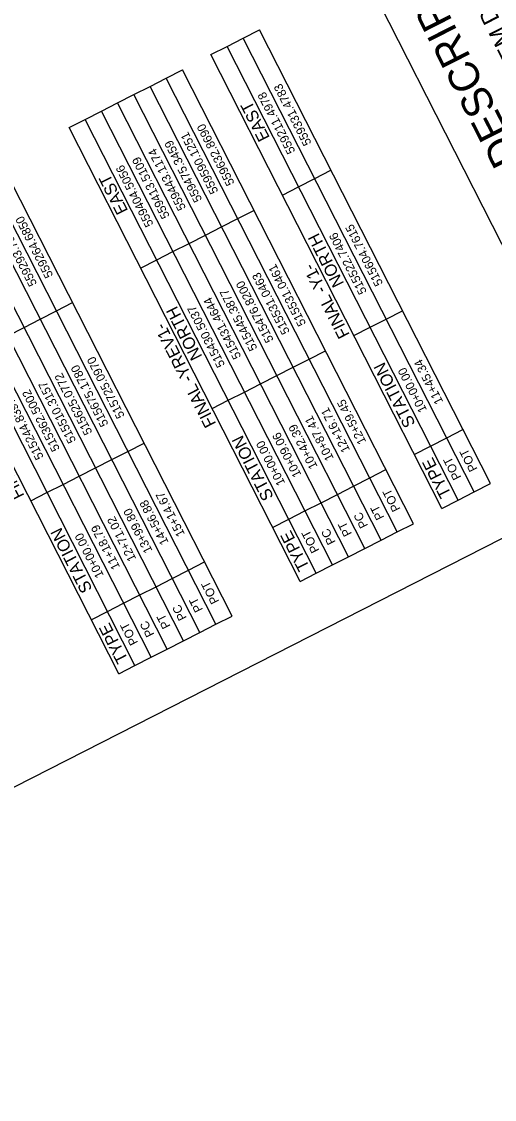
# Model space of a CAD drawing. Extents: x 558500 to 560321, y 514546 to 516470.
# Drawn here: x 559601 to 559874, y 514578 to 515201 of the extents above; entities that cross this region are included whole.
import ezdxf

# ---------------------------------------------------------------- set-up
doc = ezdxf.new("R2010")
doc.units = 0
for name, color, linetype in [('CTL Sheet Border CELL', 7, 'Continuous'), ('CTL Sheet Datum Description CELL', 7, 'Continuous'), ('CTL Sheet Notes CELL', 7, 'Continuous'), ('CTL Sheet Table Cell', 7, 'Continuous'), ('CTL Sheet Text', 7, 'Continuous')]:
    doc.layers.add(name, color=color, linetype=linetype)

msp = doc.modelspace()

# ---------------------------------------------------------------- linework, layer by layer
at = {"layer": 'CTL Sheet Border CELL'}
msp.add_line((559241.86, 514578.38), (560218.25, 515075.49), dxfattribs=at)
at = {"layer": 'CTL Sheet Datum Description CELL'}
msp.add_lwpolyline([(560206.55, 515078.89), (560011.23, 515462.53), (559747.67, 515328.35), (559942.99, 514944.71)], close=True, dxfattribs=at)
at = {"layer": 'CTL Sheet Table Cell'}
for p, q in [((559719.35, 515186.36), (559728.7, 515191.12)), ((559728.7, 515191.12), (559738.06, 515195.89)), ((559862.09, 514929.12), (559728.7, 515191.12)), ((559871.45, 514933.89), (559738.06, 515195.89)), ((559709.99, 515181.59), (559719.35, 515186.36)), ((559852.74, 514924.36), (559719.35, 515186.36)), ((559843.38, 514919.6), (559709.99, 515181.59)), ((559684.25, 515168.01), (559693.61, 515172.78)), ((559827, 514910.78), (559693.61, 515172.78)), ((559674.9, 515163.25), (559684.25, 515168.01)), ((559817.64, 514906.02), (559684.25, 515168.01)), ((559665.54, 515158.49), (559674.9, 515163.25)), ((559808.29, 514901.25), (559674.9, 515163.25)), ((559646.82, 515148.96), (559656.18, 515153.72)), ((559656.18, 515153.72), (559665.54, 515158.49)), ((559789.57, 514891.72), (559656.18, 515153.72)), ((559798.93, 514896.49), (559665.54, 515158.49)), ((559637.47, 515144.19), (559646.82, 515148.96)), ((559780.22, 514886.96), (559646.82, 515148.96)), ((559628.11, 515139.43), (559637.47, 515144.19)), ((559770.86, 514882.2), (559637.47, 515144.19)), ((559761.5, 514877.43), (559628.11, 515139.43)), ((559722.29, 514857.48), (559588.9, 515119.47)), ((559703.57, 514847.95), (559570.18, 515109.95)), ((559712.93, 514852.71), (559579.54, 515114.71)), ((559760.63, 515105.26), (559769.99, 515110.03)), ((559769.99, 515110.03), (559779.35, 515114.79)), ((559694.22, 514843.18), (559560.83, 515105.18)), ((559751.28, 515100.5), (559760.63, 515105.26)), ((559684.86, 514838.42), (559551.47, 515100.42)), ((559675.5, 514833.66), (559542.11, 515095.65)), ((559725.54, 515086.92), (559734.9, 515091.68)), ((559656.79, 514824.13), (559523.4, 515086.13)), ((559666.15, 514828.89), (559532.76, 515090.89)), ((559716.18, 515082.15), (559725.54, 515086.92)), ((559706.83, 515077.39), (559716.18, 515082.15)), ((559688.11, 515067.86), (559697.47, 515072.63)), ((559697.47, 515072.63), (559706.83, 515077.39)), ((559678.76, 515063.1), (559688.11, 515067.86)), ((559669.4, 515058.33), (559678.76, 515063.1)), ((559620.83, 515033.61), (559630.19, 515038.38)), ((559611.47, 515028.85), (559620.83, 515033.61)), ((559811.28, 515028.93), (559820.64, 515033.7)), ((559592.76, 515019.32), (559602.11, 515024.09)), ((559602.11, 515024.09), (559611.47, 515028.85)), ((559792.56, 515019.4), (559801.92, 515024.17)), ((559801.92, 515024.17), (559811.28, 515028.93)), ((559766.83, 515005.82), (559776.19, 515010.59)), ((559757.47, 515001.06), (559766.83, 515005.82)), ((559748.11, 514996.3), (559757.47, 515001.06)), ((559738.76, 514991.53), (559748.11, 514996.3)), ((559720.04, 514982), (559729.4, 514986.77)), ((559729.4, 514986.77), (559738.76, 514991.53)), ((559710.69, 514977.24), (559720.04, 514982)), ((559846.21, 514960.31), (559855.57, 514965.08)), ((559662.12, 514952.52), (559671.47, 514957.28)), ((559827.5, 514950.79), (559836.86, 514955.55)), ((559836.86, 514955.55), (559846.21, 514960.31)), ((559652.76, 514947.76), (559662.12, 514952.52)), ((559634.04, 514938.23), (559643.4, 514942.99)), ((559643.4, 514942.99), (559652.76, 514947.76)), ((559801.76, 514937.21), (559811.12, 514941.97)), ((559624.69, 514933.46), (559634.04, 514938.23)), ((559792.41, 514932.44), (559801.76, 514937.21)), ((559615.33, 514928.7), (559624.69, 514933.46)), ((559783.05, 514927.68), (559792.41, 514932.44)), ((559862.09, 514929.12), (559871.45, 514933.89)), ((559605.97, 514923.94), (559615.33, 514928.7)), ((559773.69, 514922.91), (559783.05, 514927.68)), ((559843.38, 514919.6), (559852.74, 514924.36)), ((559852.74, 514924.36), (559862.09, 514929.12)), ((559754.98, 514913.39), (559764.34, 514918.15)), ((559764.34, 514918.15), (559773.69, 514922.91)), ((559745.62, 514908.62), (559754.98, 514913.39)), ((559817.64, 514906.02), (559827, 514910.78)), ((559808.29, 514901.25), (559817.64, 514906.02)), ((559798.93, 514896.49), (559808.29, 514901.25)), ((559789.57, 514891.72), (559798.93, 514896.49)), ((559697.05, 514883.9), (559706.41, 514888.67)), ((559770.86, 514882.2), (559780.22, 514886.96)), ((559780.22, 514886.96), (559789.57, 514891.72)), ((559687.69, 514879.14), (559697.05, 514883.9)), ((559761.5, 514877.43), (559770.86, 514882.2)), ((559668.98, 514869.61), (559678.34, 514874.37)), ((559678.34, 514874.37), (559687.69, 514879.14)), ((559659.62, 514864.85), (559668.98, 514869.61)), ((559650.27, 514860.08), (559659.62, 514864.85)), ((559640.91, 514855.32), (559650.27, 514860.08)), ((559712.93, 514852.71), (559722.29, 514857.48)), ((559703.57, 514847.95), (559712.93, 514852.71)), ((559684.86, 514838.42), (559694.22, 514843.18)), ((559694.22, 514843.18), (559703.57, 514847.95)), ((559675.5, 514833.66), (559684.86, 514838.42)), ((559666.15, 514828.89), (559675.5, 514833.66)), ((559656.79, 514824.13), (559666.15, 514828.89))]:
    msp.add_line(p, q, dxfattribs=at)

# ---------------------------------------------------------------- texts
at = {"layer": 'CTL Sheet Datum Description CELL'}
for s, height, p in [('THE LOCALIZED COORDINATE SYSTEM DEVELOPED FOR THIS PROJECT', 9.6863, (559991.27, 514977.63)), ('IS BASED ON THE STATE PLANE COORDINATES ESTABLISHED BY', 9.6863, (559999.9, 514998.26)), ('WITH NAD 83/95 STATE PLANE GRID COORDINATES OF', 9.6863, (560017.11, 515039.63)), ('NCDOT FOR MONUMENT "GPS 101"', 9.6863, (559972.59, 515089.5)), ('DATUM DESCRIPTION', 17.5, (559930.57, 515042.18))]:
    msp.add_text(s, height=height, rotation=116.98193, dxfattribs=at).set_placement(p)
at = {"layer": 'CTL Sheet Notes CELL'}
for s, p in [('EAST', (559744.21, 515133.67)), ('EAST', (559662.33, 515091.51)), ('NORTH', (559787.07, 515049.48)), ('FINAL -Y1-', (559790.35, 515019.89)), ('NORTH', (559705.19, 515007.32)), ('FINAL -YREV1-', (559713.2, 514968.44)), ('STATION', (559828.33, 514968.44)), ('FINAL -L-', (559602.46, 514926.97)), ('STATION', (559746.45, 514926.27)), ('TYPE', (559849.01, 514927.81)), ('STATION', (559641.74, 514872.97)), ('TYPE', (559767.14, 514885.65)), ('TYPE', (559662.42, 514832.35))]:
    msp.add_text(s, height=7, rotation=116.98193, dxfattribs=at).set_placement(p)
at = {"layer": 'CTL Sheet Text'}
for s, p in [('559211.4978', (559758.9, 515125.75)), ('559331.4783', (559768.26, 515130.51)), ('559632.8690', (559723.81, 515107.41)), ('559590.1251', (559714.45, 515102.64)), ('559475.3459', (559705.09, 515097.88)), ('559443.1174', (559695.74, 515093.11)), ('559404.5056', (559677.02, 515083.59)), ('559413.5109', (559686.38, 515088.35)), ('559264.6850', (559619.09, 515054.1)), ('559293.7996', (559609.74, 515049.34)), ('515522.7406', (559800.19, 515044.65)), ('515604.7615', (559809.54, 515049.42)), ('515531.0461', (559765.09, 515026.31)), ('515531.0463', (559755.74, 515021.55)), ('515476.8200', (559746.38, 515016.78)), ('515445.3877', (559737.02, 515012.02)), ('515430.5037', (559718.31, 515002.49)), ('515431.4644', (559727.67, 515007.25)), ('515725.0970', (559660.38, 514973.01)), ('11+45.34', (559844.28, 514981.19)), ('515625.0772', (559641.67, 514963.48)), ('515675.1780', (559651.02, 514968.24)), ('10+00.00', (559834.92, 514976.43)), ('515510.3157', (559632.31, 514958.71)), ('515362.5002', (559622.95, 514953.95)), ('515244.8397', (559613.6, 514949.19)), ('12+59.45', (559799.83, 514958.09)), ('10+87.41', (559781.12, 514948.56)), ('12+16.71', (559790.47, 514953.32)), ('10+42.39', (559771.76, 514943.79)), ('10+09.06', (559762.4, 514939.03)), ('10+00.00', (559753.04, 514934.27)), ('POT', (559854.7, 514937.58)), ('POT', (559864.06, 514942.34)), ('POT', (559819.61, 514919.23)), ('14+56.88', (559685.76, 514900.02)), ('15+14.67', (559695.12, 514904.78)), ('13+99.80', (559676.4, 514895.25)), ('PC ', (559800.9, 514909.7)), ('PT ', (559810.25, 514914.47)), ('12+71.02', (559667.05, 514890.49)), ('PT ', (559791.54, 514904.94)), ('10+00.00', (559648.33, 514880.96)), ('11+18.79', (559657.69, 514885.73)), ('POT', (559772.83, 514895.41)), ('PC ', (559782.18, 514900.18)), ('POT', (559714.9, 514865.93)), ('PT ', (559705.54, 514861.16)), ('PC ', (559696.18, 514856.4)), ('PT ', (559686.83, 514851.64)), ('POT', (559668.11, 514842.11)), ('PC ', (559677.47, 514846.87))]:
    msp.add_text(s, height=5, rotation=116.98193, dxfattribs=at).set_placement(p)

doc.saveas('drawing.dxf')
